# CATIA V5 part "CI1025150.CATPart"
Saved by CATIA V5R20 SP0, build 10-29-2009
Part number: CI1025150
Bounding box of the stored display mesh (mm): x -24 to 24, y -20.11 to 184.5, z -26.352 to 28.386
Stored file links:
  C:\Users\Raffaele\Desktop\3D X SITO CF\BOLEX\19-INCLINED ASSEMBLY REF_CI\CI1025150.CATPart
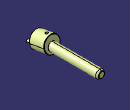
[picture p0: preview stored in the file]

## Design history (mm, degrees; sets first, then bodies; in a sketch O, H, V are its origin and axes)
Set1
  DatumSurface1 to DatumSurface16 "MANIFOLD_SOLID_BREP #393"
  DatumSurface17 to DatumSurface39 "MANIFOLD_SOLID_BREP #1138"
Body1 (main body)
